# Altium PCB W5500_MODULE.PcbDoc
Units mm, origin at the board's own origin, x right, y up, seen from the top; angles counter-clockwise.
Board outline 30 x 34 mm, 2 copper layers (Top Layer, Bottom Layer); 44 components, 75 nets, 250 pads, 86 vias.
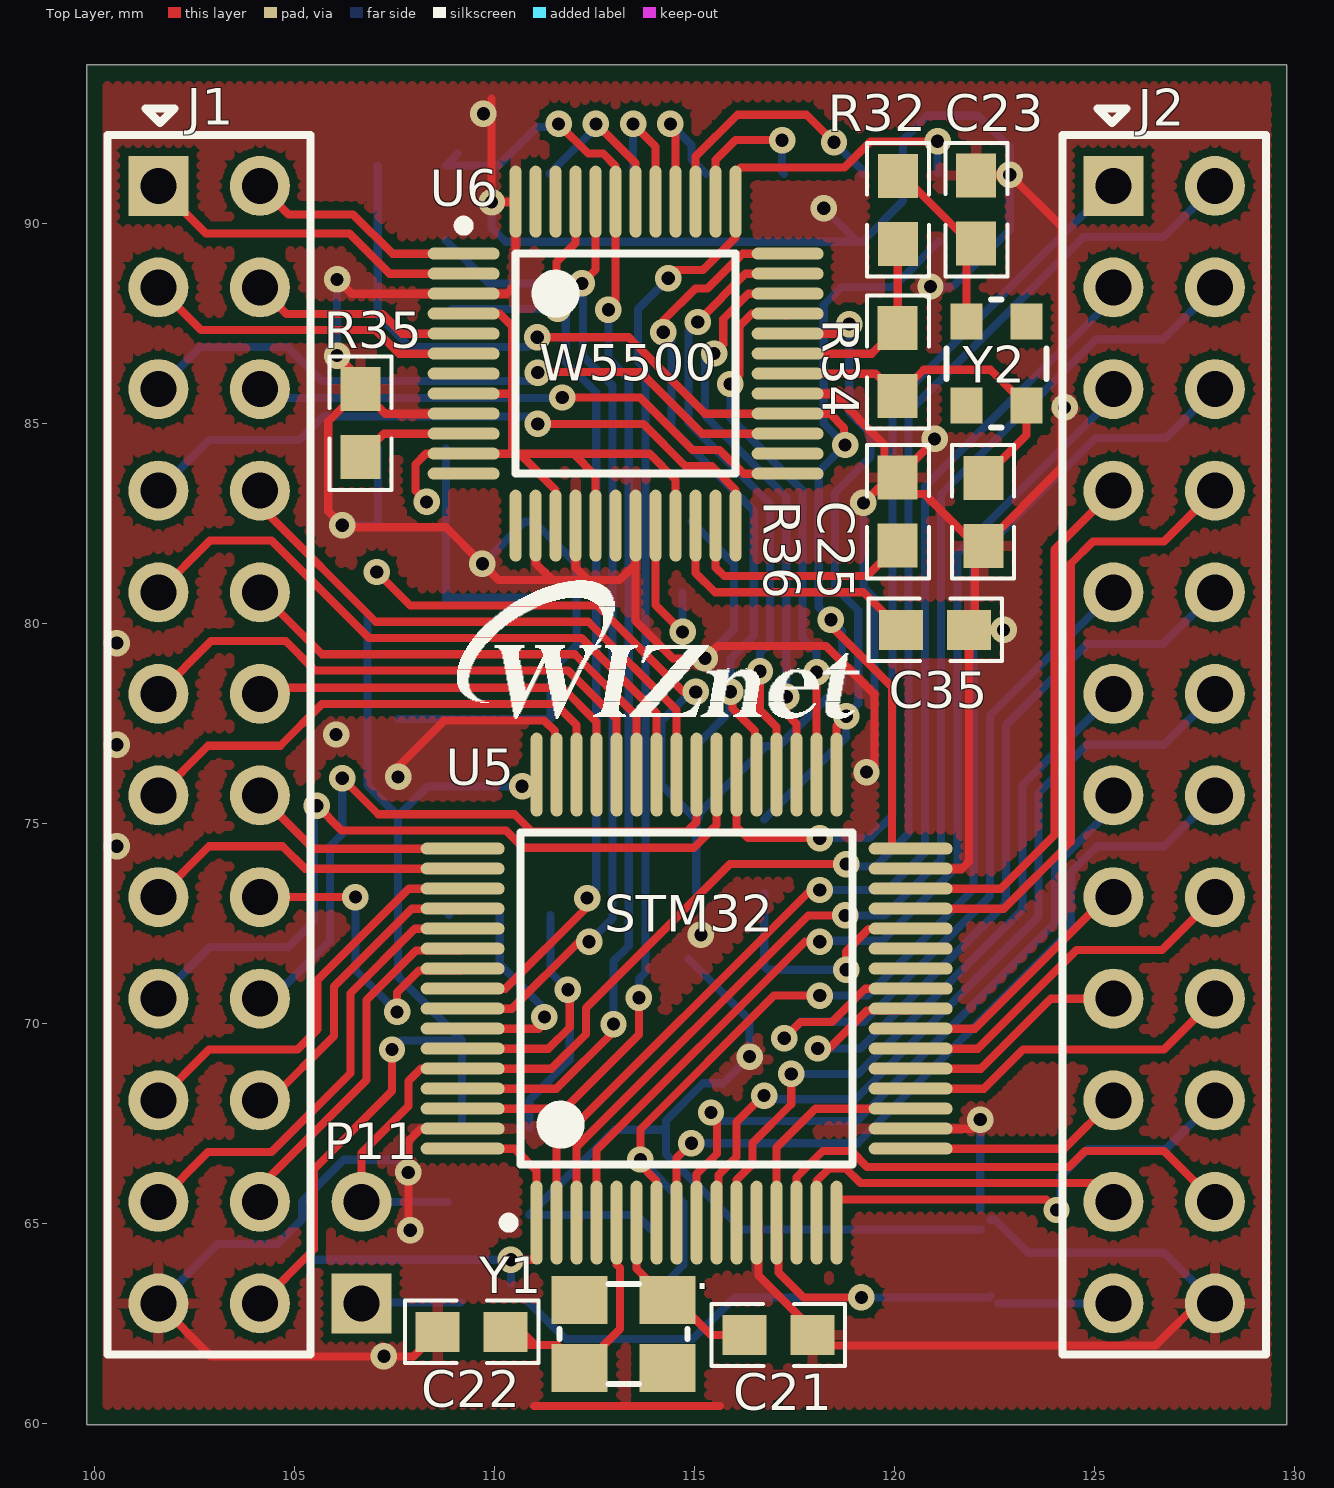
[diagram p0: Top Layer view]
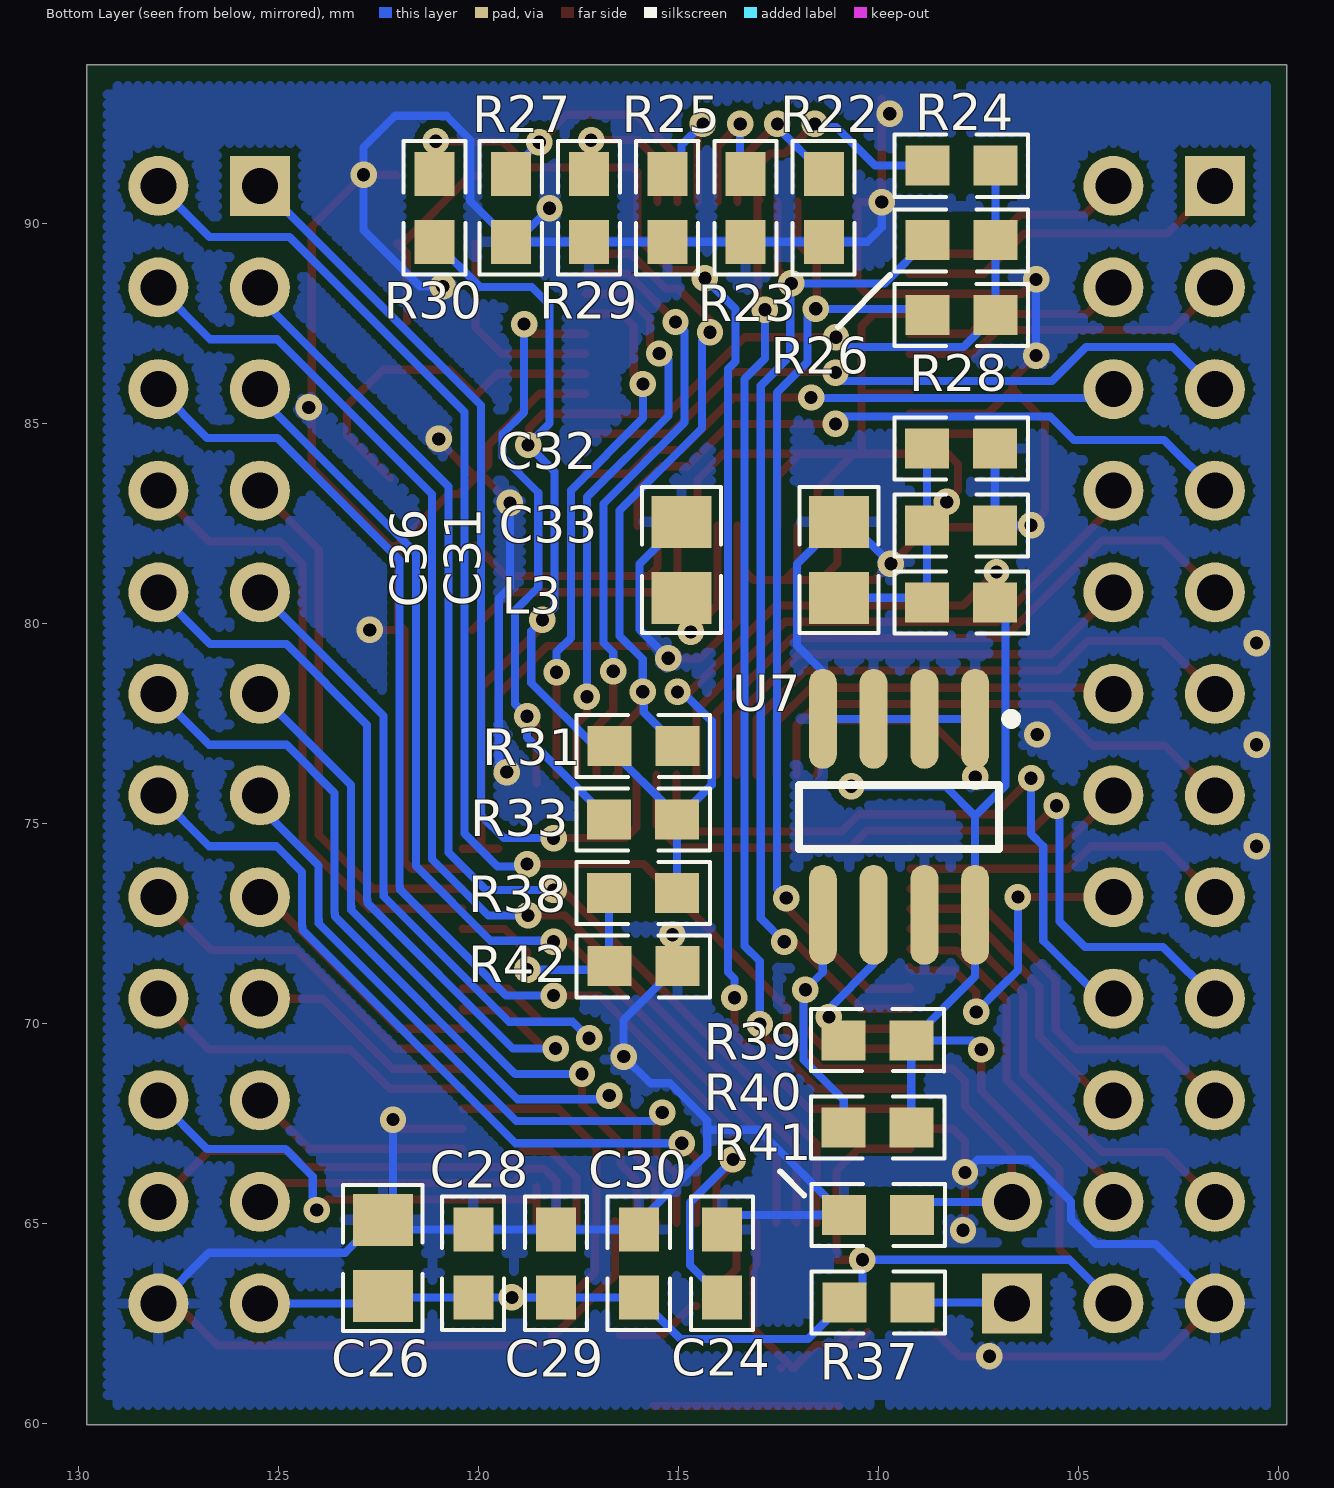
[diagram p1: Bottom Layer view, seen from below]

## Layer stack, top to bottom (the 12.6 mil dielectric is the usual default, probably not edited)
Top Layer: signal copper 0.0356
Dielectric: dielectric 0.32, FR-4, Dk 4.8
Bottom Layer: signal copper 0.0356

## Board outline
99.81,59.963 129.806,59.963 129.806,93.961 99.81,93.961

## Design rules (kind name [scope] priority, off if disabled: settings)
Clearance [All] p1: gap=0.203
PolygonConnect [IsVia] p1: connectstyle=Direct reliefconductorwidth=0.254 reliefentries=4 polygonreliefangle="90 Angle"
PolygonConnect PolygonConnect_1 [All] p2: connectstyle=Relief reliefconductorwidth=0.254 reliefentries=4 polygonreliefangle="90 Angle"
RoutingVias [All] p1: holewidth=0.33 width=0.66 viastyle="Through Hole" minholewidth=0.33 minwidth=0.66 maxholewidth=0.33 maxwidth=0.66
SilkscreenOverComponentPads [All] p1: minsilkscreentomaskgap=0.254
SolderMaskExpansion [All] p1: expansion=0.102
TestPointUsage [All] p1: valid=0 allowmultiple=FALSE
Testpoint [All] p1: side=15 testpointundercomponent=TRUE minsize=1.016 maxsize=2.54 preferedsize=1.524 minholesize=0 maxholesize=1.016 preferedholesize=0.813 testpointgrid=0.025 style=1023 order=0123456789
Width [All] p1: maxlimit=0.203 minlimit=0.203 preferedwidth=0.203
23 further rules are at their usual default settings.

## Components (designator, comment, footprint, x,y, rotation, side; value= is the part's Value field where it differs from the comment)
C21 "Cap" CR0603 117.069,62.332 r0 top
C22 "Cap" CR0603 109.474,62.154 r180 top
C23 "Cap" CR0603 121.92,90.305 r90 top
C24 "Cap" CR0603 113.792,64.033 r270 bottom
C25 "Cap" CR0603 122.352,82.821 r270 top
C26 "Cap2" CR0805 122.453,64.16 r90 bottom
C28 "Cap" CR0603 120.015,64.033 r270 bottom
C29 "Cap" CR0603 117.945,64.033 r270 bottom
C30 "Cap" CR0603 115.875,64.033 r270 bottom
C31 "Cap2" CR0805 111.049,81.61 r90 bottom
C32 "Cap" CR0603 107.908,84.237 r0 bottom
C33 "Cap" CR0603 107.908,82.314 r0 bottom
C35 "Cap" CR0603 121.056,79.705 r180 top
C36 "Cap2" CR0805 114.986,81.61 r90 bottom
J1 "Header 12X2" HDR2X12 101.6,90.932 r270 top locked
J2 "Header 12X2" HDR2X12 125.476,90.932 r270 top locked
L3 "Inductor" cr0603 107.908,80.391 r0 bottom
P11 "2.0间距焊盘" HDR1X2 106.68,62.992 r90 top locked
R22 "Res1" CR0603 111.252,90.424 r270 bottom
R23 "Res1" CR0603 113.208,90.424 r270 bottom
R24 "Res1" CR0603 107.975,91.567 r180 bottom
R25 "Res1" CR0603 115.164,90.424 r270 bottom
R26 "Res1" CR0603 107.975,89.7 r180 bottom
R27 "Res1" CR0603 119.075,90.424 r270 bottom
R28 "Res1" CR0603 107.975,87.833 r180 bottom
R29 "Res1" CR0603 117.119,90.424 r270 bottom
R30 "Res1" CR0603 120.98,90.424 r270 bottom
R31 "Res1" CR0603 115.926,77.058 r180 bottom
R32 "Res1" CR0603 120.218,90.373 r270 top
R33 "Res1" CR0603 115.858,74.962 r0 bottom
R34 "Res1" CR0603 119.957,86.495 r90 top
R35 "Res1" CR0603 106.528,84.963 r90 top
R36 "Res1" CR0603 119.957,82.753 r90 top
R37 "Res1" CR0603 110.05,63.144 r180 bottom
R38 "Res1" CR0603 115.858,73.126 r0 bottom
R39 "Res1" CR0603 110.002,69.444 r0 bottom
R40 "Res1" CR0603 109.992,67.259 r0 bottom
R41 "Res1" CR0603 109.982,65.075 r0 bottom
R42 "Res1" CR0603 115.926,71.552 r180 bottom
U5 "STM32F103RC" LQFP64_M 114.808,70.612 r90 top locked
U6 "W5500" TQFP48_N 113.284,86.487 r0 top locked
U7 "EEPROM" "8 pin SOIC_M" 109.499,75.159 r270 bottom locked
Y1 "XTAL 8.0MHz" 4pin晶振（FA238）#1 113.233,62.23 r180 top
Y2 "XTAL 25.0MHz" 4pin晶振（FA238）#2 122.55,86.488 r90 top

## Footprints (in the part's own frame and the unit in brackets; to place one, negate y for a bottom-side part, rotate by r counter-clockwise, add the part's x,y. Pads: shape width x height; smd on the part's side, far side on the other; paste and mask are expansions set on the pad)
4pin晶振（FA238）#1 [mm] "4pin晶振（FA238）"
  rect 1.4x1.2 smd: 1(-1.1,-0.85) 2(1.1,-0.85) 3(1.1,0.85) 4(-1.1,0.85)
  silkscreen extent -1.6,-1.25 1.6,1.25
4pin晶振（FA238）#2 [mm]
  rect 0.9x0.8 smd: 1(-1.05,-0.75) 2(1.05,-0.75) 3(1.05,0.75) 4(-1.05,0.75)
  silkscreen extent -1.6,-1.25 1.6,1.25
"8 pin SOIC_M" [mm] "8-Pin Small Outline Integrated Circuit 1.27 mm Pitch, IPC Low Density"
  oval 2.5x0.7 smd: 1(-2.45,1.905) 2(-2.45,0.635) 3(-2.45,-0.635) 4(-2.45,-1.905) 5(2.45,-1.905) 6(2.45,-0.635) 7(2.45,0.635) 8(2.45,1.905)
  silkscreen extent -2.57,-2.5 0.8,2.93, body extent -2,-2.5 2,2.5, height 1.91
CR0603 [mm]
  rect 1.1x1 smd: 1(-0.811,-0.127) 2(0.889,-0.127)
  silkscreen extent -1.63,-0.91 1.7,0.65
cr0603 [mm]
  rect 1.1x1 smd: 1(-0.811,-0.127) 2(0.889,-0.127)
  silkscreen extent -1.63,-0.91 1.7,0.65
CR0805 [mm]
  rect 1.3x1.5 smd: 1(-0.975,-0.051) 2(0.925,-0.051)
  silkscreen extent -1.85,-1.04 1.8,0.94
HDR1X2 [mm] "Connector; Header; 2 Position"
  rect 1.5x1.5 hole 0.9: 1(0,0)
  round 1.5 hole 0.9: 2(2.54,0)
HDR2X12 [mm] "Connector; Header; 12x2 Position"
  rect 1.5x1.5 hole 0.9: 1(0,0)
  round 1.5 hole 0.9: 2(0,2.54) 3(2.54,0) 4(2.54,2.54) 5(5.08,0) 6(5.08,2.54) 7(7.62,0) 8(7.62,2.54) 9(10.16,0) 10(10.16,2.54) 11(12.7,0) 12(12.7,2.54) 13(15.24,0) 14(15.24,2.54) 15(17.78,0) 16(17.78,2.54) 17(20.32,0) 18(20.32,2.54) 19(22.86,0) 20(22.86,2.54) 21(25.4,0) 22(25.4,2.54) 23(27.94,0) 24(27.94,2.54)
  silkscreen extent -1.27,-1.27 29.21,3.81
LQFP64_M [mm] "Thin QFP, 64-Leads, Body 10x10mm, Pitch 0.5mm, IPC Low Density"
  oval 2.1x0.3 smd: 1(-5.6,3.75) 2(-5.6,3.25) 3(-5.6,2.75) 4(-5.6,2.25) 5(-5.6,1.75) 6(-5.6,1.25) 7(-5.6,0.75) 8(-5.6,0.25) 9(-5.6,-0.25) 10(-5.6,-0.75) 11(-5.6,-1.25) 12(-5.6,-1.75) 13(-5.6,-2.25) 14(-5.6,-2.75) 15(-5.6,-3.25) 16(-5.6,-3.75) 33(5.6,-3.75) 34(5.6,-3.25) 35(5.6,-2.75) 36(5.6,-2.25) 37(5.6,-1.75) 38(5.6,-1.25) 39(5.6,-0.75) 40(5.6,-0.25) 41(5.6,0.25) 42(5.6,0.75) 43(5.6,1.25) 44(5.6,1.75) 45(5.6,2.25) 46(5.6,2.75) 47(5.6,3.25) 48(5.6,3.75)
  oval 0.3x2.1 smd: 17(-3.75,-5.6) 18(-3.25,-5.6) 19(-2.75,-5.6) 20(-2.25,-5.6) 21(-1.75,-5.6) 22(-1.25,-5.6) 23(-0.75,-5.6) 24(-0.25,-5.6) 25(0.25,-5.6) 26(0.75,-5.6) 27(1.25,-5.6) 28(1.75,-5.6) 29(2.25,-5.6) 30(2.75,-5.6) 31(3.25,-5.6) 32(3.75,-5.6) 49(3.75,5.6) 50(3.25,5.6) 51(2.75,5.6) 52(2.25,5.6) 53(1.75,5.6) 54(1.25,5.6) 55(0.75,5.6) 56(0.25,5.6) 57(-0.25,5.6) 58(-0.75,5.6) 59(-1.25,5.6) 60(-1.75,5.6) 61(-2.25,5.6) 62(-2.75,5.6) 63(-3.25,5.6) 64(-3.75,5.6)
  silkscreen extent -5.72,-4.15 4.15,4.57, body extent -5,-5 5,5, height 1.6
TQFP48_N [mm] "Thin QFP, 48-Leads, Body 7x7mm, Pitch 0.5mm, IPC Medium Density"
  oval 1.8x0.3 smd: 1(-4.05,2.75) 2(-4.05,2.25) 3(-4.05,1.75) 4(-4.05,1.25) 5(-4.05,0.75) 6(-4.05,0.25) 7(-4.05,-0.25) 8(-4.05,-0.75) 9(-4.05,-1.25) 10(-4.05,-1.75) 11(-4.05,-2.25) 12(-4.05,-2.75) 25(4.05,-2.75) 26(4.05,-2.25) 27(4.05,-1.75) 28(4.05,-1.25) 29(4.05,-0.75) 30(4.05,-0.25) 31(4.05,0.25) 32(4.05,0.75) 33(4.05,1.25) 34(4.05,1.75) 35(4.05,2.25) 36(4.05,2.75)
  oval 0.3x1.8 smd: 13(-2.75,-4.05) 14(-2.25,-4.05) 15(-1.75,-4.05) 16(-1.25,-4.05) 17(-0.75,-4.05) 18(-0.25,-4.05) 19(0.25,-4.05) 20(0.75,-4.05) 21(1.25,-4.05) 22(1.75,-4.05) 23(2.25,-4.05) 24(2.75,-4.05) 37(2.75,4.05) 38(2.25,4.05) 39(1.75,4.05) 40(1.25,4.05) 41(0.75,4.05) 42(0.25,4.05) 43(-0.25,4.05) 44(-0.75,4.05) 45(-1.25,4.05) 46(-1.75,4.05) 47(-2.25,4.05) 48(-2.75,4.05)
  silkscreen extent -4.17,-2.75 2.75,3.57, body extent -3.5,-3.5 3.5,3.5, height 1.6

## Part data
C21 C22 C23 C24 C25 C26 C28 C29 C30 C31 C32 C33 C35 C36: "Capacitor"
J1 J2: "Header, 12-Pin, Dual row"
P11: library part "Header 2", "Header, 2-Pin"
R22 R23 R24 R25 R26 R27 R28 R29 R30 R31 R32 R33 R34 R35 R36 R37 R38 R39 R40 R41 R42: "Resistor"
U7: library part 24XX01, "24XX01"
Y1 Y2: library part XTAL, "Crystal Oscillator"

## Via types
v1: diameter 0.66, hole 0.33, Top Layer to Bottom Layer, tented both sides, 81 vias
v2: diameter 0.66, hole 0.33, Top Layer to Bottom Layer, 5 vias

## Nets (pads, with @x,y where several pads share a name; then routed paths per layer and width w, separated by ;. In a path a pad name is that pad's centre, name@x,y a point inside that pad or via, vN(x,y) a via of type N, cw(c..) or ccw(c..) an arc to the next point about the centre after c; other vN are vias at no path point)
ACTLED: J1.5 U6.27 | length 16.9
  Top Layer w0.203: v1@111.346,86.276 113.657,86.276 115.196,84.737 U6.27
  Bottom Layer w0.203: J1.5 102.655,86.907 104.826,86.907 105.677,86.055 v1@111.125,86.055
  other v1: 111.086,86.264
BOOT0: J2.2 P11.2 R41.1 U5.60 | length 42.2
  Top Layer w0.203: P11.2@106.74,65.532 P11.2 106.68,66.751 107.853,67.924 107.853,68.55 108.165,68.862 U5.60 ; U5.60@109.163,68.817 U5.60 ; v1(118.796,73.977) 115.887,73.977 112.293,70.383 112.293,69.723 111.432,68.862 U5.60
  Bottom Layer w0.203: P11.2@107.01,65.202 P11.2 R41.1@108.841,65.532 ; v1@118.859,73.914 119.532,73.914 120.357,74.739 120.357,85.28 124.732,89.654 126.374,89.654 ; 126.374,89.651 126.735,89.651 J2.2
DUPLED: U6.26
GND: C21.2 C22.2 C23.2 C24.1 C25.2 C26.2 C28.1 C29.1 C30.1 C31.2 C32.1 C33.1 C35.1 C36.2 J1.23 J2.24 R22.2 R23.2 R25.2 R27.2 R29.2 R35.2 R36.2 R41.2 R42.2 U5.12 U5.18 U5.31 U5.47 U5.63 U6.3 U6.9 U6.14 U6.16 U6.19 U6.29 U6.48 U7.1 U7.2 U7.3 U7.4 U7.7 | length 199.6
  Top Layer w0.203: J1.23 102.921,61.671 v1(107.239,61.671) 107.975,61.671 C22.2 ; v1(106.07,86.69) 106.655,86.106 R35.2 ; v1(106.07,88.595) 106.429,88.237 U6.3 110.31,88.237 110.534,88.461 U6.48 ; v1@107.606,76.417 108.755,77.567 111.246,77.567 111.513,77.3 111.513,76.257 U5.47 ; v1(107.899,64.821) 107.853,64.867 107.853,67.05 108.165,67.362 U5.63 ; U6.9 107.27,85.237 R35.2 ; 109.931,93.116 v1(109.931,90.526) U6.48@110.523,90.526 ; 110.998,60.427 115.646,60.427 ; U6.14 111.034,81.498 111.455,81.077 ; U6.16 112.034,81.387 112.344,81.077 ; U6.19 113.534,81.479 ; U5.12@116.603,65.057 U5.12 116.603,64.967 116.603,63.695 116.883,63.416 118.094,62.205 C21.2@118.186,62.205 ; U6.29 118.479,85.737 119.758,84.458 119.758,83.968 R36.2 ; C21.2@118.454,61.937 126.531,61.937 127.586,62.992 J2.24 ; v1(119.228,83.007) 119.863,83.642 R36.2 ; v1(119.304,76.276) 119.507,76.479 119.507,78.22 118.296,79.431 115.575,79.431 v1(115.265,79.121) 114.469,79.121 113.534,80.056 113.534,81.479 ; U5.31 121.69,73.862 121.867,74.039 C35.1 ; v1(121.006,84.607) 121.006,84.563 R36.2 ; 121.845,67.362 U5.18 121.921,67.362 v1(122.149,67.589) ; C25.2@121.979,81.932 C25.2 ; C23.2 122.064,91.211 v1(122.885,91.211) 124.181,89.916 124.181,83.888 C25.2 ; v1(122.733,79.832) C35.1 ; R35.2 105.85,85.047 105.85,82.796 v1(106.197,82.448) 106.248,82.398 108.788,82.398 v1(109.703,81.483) 110.109,81.077 111.455,81.077 ; 111.455,81.077 112.344,81.077 ; 112.344,81.077 113.132,81.077 113.534,81.479 ; R36.2 120.494,83.233 120.754,83.233 122.055,81.932 C25.2 ; C35.1 122.022,79.986 122.022,81.729 C25.2
  Bottom Layer w0.203: J1.23 103.085,64.477 104.577,64.477 105.195,65.095 105.195,65.539 106.243,66.587 107.53,66.587 v1(107.848,66.269) ; v1(106.07,86.69) v1(106.07,88.595) ; v1@106.205,82.441 C33.1 C32.1 ; U7.1 U7.2 U7.3 U7.4 111.404,78.791 112.053,79.439 112.053,81.48 C31.2 110.754,82.535 v1(109.703,81.483) ; U7.7@108.839,72.734 U7.7 ; v1(109.931,90.526) 109.931,89.891 110.287,89.535 R22.2 R23.2 R25.2 R29.2 R27.2@119.075,89.535 ; C24.1 113.562,65.202 R41.2 113.005,67.335 114.293,67.335 ; R42.2@114.859,71.603 R42.2 116.383,70.079 v1(116.383,69.164) 115.716,68.497 115.22,68.497 114.293,67.571 114.293,67.335 ; C36.2 115.99,81.48 115.99,79.846 v1(115.265,79.121) ; v1(118.237,90.373) R27.2@119.075,89.535 ; v1@119.202,76.225 119.506,76.529 119.506,80.621 119.228,80.899 v1(119.228,83.007) ; v1(120.904,88.417) 121.471,88.417 122.885,89.832 v1(122.885,91.211) 122.885,91.897 122.098,92.684 120.819,92.684 120.218,92.084 120.218,90.551 R27.2 R27.2@119.075,89.535 ; C26.2@122.149,65.339 v1(122.149,67.589) ; C26.2@122.162,64.844 C28.1 C29.1 C30.1 116.002,65.024 114.293,66.733 114.293,67.335 ; C26.2 122.519,65.085 123.342,64.262 124.866,64.262 ; 124.485,64.262 124.866,64.262 ; J2.24 126.746,64.262 124.866,64.262
  other v1: 115.164,72.212 100.559,74.422 107.594,76.155 100.559,76.962 106.045,77.216 100.559,79.502 124.257,85.395 109.728,92.735
I2C_SCL: R39.2 U5.58 U7.6 | length 8.7
  Top Layer w0.203: U5.58@109.253,69.907 U5.58 ; U5.58@110.251,69.862 U5.58 ; 110.756,69.862 U5.58 ; v1@111.112,69.862 U5.58
  Bottom Layer w0.203: U7.6@110.134,71.78 U7.6 110.134,71.476 111.252,70.358 R39.2@111.252,69.931
  other v1: 111.252,70.155
I2C_SDA: R40.2 U5.59 U7.5 | length 10.6
  Top Layer w0.203: U5.59 111.357,69.362 111.887,69.892 v1@111.887,70.79
  Bottom Layer w0.203: R40.2 110.881,68.079 111.887,69.085 111.887,70.79 v1(111.839,70.838) 111.404,71.272 U7.5 U7.5@111.404,71.806
JTDI: J1.15 U5.50 | length 8.4
  Top Layer w0.203: J1.15 102.87,74.422 104.707,74.422 105.267,73.862 U5.50
LINKLED: J1.6 U6.25 | length 14.4
  Top Layer w0.203: v1@111.943,85.641 113.64,85.641 114.95,84.331 115.634,84.331 116.228,83.737 U6.25
  Bottom Layer w0.203: J1.6@104.546,86.258 J1.6 104.363,85.629 v1@111.696,85.629
  other v1: 111.696,85.641
NetC23_1: C23.1 R32.1 Y2.3 | length 4.8
  Top Layer w0.203: R32.1 120.22,91.184 121.91,89.494 C23.1 ; Y2.3 121.8,89.248 C23.1 ; C23.1@121.986,89.494 C23.1
NetC25_1: C25.1 R34.1 U6.30 Y2.1 | length 9.4
  Top Layer w0.203: U6.30 119.532,86.237 R34.1 ; R34.1@120.155,85.684 R34.1 ; C25.1 123.3,84.707 Y2.1 ; Y2.1@123.3,85.2 Y2.1 ; R34.1 120.735,86.335 122.403,86.335 Y2.1
NetC35_2: C35.2 U6.22 | length 6.9
  Top Layer w0.203: U6.22 115.034,81.257 115.519,80.772 119.228,80.772 C35.2
NetC36_1: C36.1 U6.20 | length 3.9
  Top Layer w0.203: U6.20 114.034,80.454 v1(114.706,79.781)
  Bottom Layer w0.203: v1(114.706,79.781) C36.1@114.706,80.768
NetP11_1: P11.1 R37.2 | length 2.5
  Bottom Layer w0.203: P11.1 106.705,63.017 R37.2
NetR22_1: R22.1 U6.42 | length 4
  Top Layer w0.203: v1@112.558,92.481 113.534,91.505 U6.42
  Bottom Layer w0.203: R22.1@111.404,91.26 R22.1 v1@112.549,92.405
  other v1: 112.539,92.481
NetR23_1: R23.1 U6.41 | length 3.3
  Top Layer w0.203: v1(113.47,92.481) 114.034,91.918 U6.41
  Bottom Layer w0.203: R23.1@113.47,91.37 v1(113.47,92.481)
NetR25_1: R25.1 U6.40 | length 3.6
  Top Layer w0.203: v1(114.402,92.481) 114.534,92.349 U6.40
  Bottom Layer w0.203: v1(114.402,92.481) 114.933,91.95 114.933,91.592 R25.1
NetR27_1: R27.1 U6.39 | length 6.3
  Top Layer w0.203: U6.39 115.034,91.669 116.075,92.71 117.805,92.71 v1(118.491,92.024)
  Bottom Layer w0.203: v1@118.542,91.973 119.202,91.313 R27.1
NetR29_1: R29.1 U6.38 | length 3.9
  Top Layer w0.203: U6.38 115.534,91.582 116.027,92.075 v1(117.196,92.075) v1@117.348,92.075
  Bottom Layer w0.203: v1(117.196,92.075) 117.196,91.286 R29.1
NetR32_2: R32.2 R34.2 U6.31 | length 5.1
  Top Layer w0.203: U6.31 119.437,86.737 R34.2 120.084,89.477 R32.2
NetR35_1: R35.1 U6.10 | length 2.8
  Top Layer w0.203: R35.1 107.24,84.737 U6.10
NetR36_1: R36.1 U6.23 | length 6
  Top Layer w0.203: U6.23 115.534,81.392 115.748,81.178 119.321,81.178 R36.1
NRESET: C24.2 J2.6 U5.7 | length 33.6
  Top Layer w0.203: v1@113.587,66.592 113.587,66.527 114.058,66.055 U5.7 ; v1(113.652,66.592) 113.652,67.348 116.992,70.688 v1(118.135,70.688) ; v1@118.118,70.671 v1(118.135,70.688) ; v1@118.161,70.688 v1(118.135,70.688)
  Bottom Layer w0.203: v1(113.652,66.592) 114.724,65.521 114.724,63.949 C24.2 ; v1@118.161,70.688 119.326,70.688 121.974,73.337 121.974,73.423 121.983,73.431 121.983,81.581 125.035,84.633 126.797,84.633 J2.6
PA0: J2.22 U5.14 | length 12.7
  Top Layer w0.203: U5.14 117.558,66.148 118.212,66.802 118.925,66.802 119.32,66.407 124.37,66.407 124.765,66.802 126.746,66.802 J2.22
PA1: J2.21 U5.15 | length 8.9
  Top Layer w0.203: U5.15 118.058,66.055 118.373,66.37 118.376,66.367 118.785,66.367 119.151,66.001 125.007,66.001 J2.21
PA2: J2.20 U5.16 | length 12
  Top Layer w0.203: U5.16 U5.16@118.558,65.904 ; U5.16@118.593,65.594 123.788,65.594 v1(124.054,65.329)
  Bottom Layer w0.203: v1(124.054,65.329) 124.155,65.43 124.155,66.167 124.841,66.853 126.797,66.853 J2.20
PA3: J2.19 U5.17 | length 5.6
  Top Layer w0.203: U5.17 124.25,66.862 125.46,68.072 J2.19
PA4: J2.18 U5.20 | length 8.5
  Top Layer w0.203: U5.20 122.239,68.362 123.219,69.342 126.746,69.342 J2.18
PA5: J2.17 U5.21 | length 5.8
  Top Layer w0.203: U5.21 122.164,68.862 123.914,70.612 J2.17
PA6: J2.16 U5.22 | length 9.2
  Top Layer w0.203: U5.22 122.089,69.362 124.559,71.831 126.695,71.831 J2.16
PA7: J2.15 U5.23 | length 6.4
  Top Layer w0.203: U5.23 122.015,69.862 125.305,73.152 J2.15
PA8: J1.8 U5.41 | length 14.5
  Top Layer w0.203: J1.8 104.35,83.102 104.35,82.721 107.036,80.035 112.348,80.035 114.558,77.825 U5.41
PA9: J1.9 U5.42 | length 16.3
  Top Layer w0.203: J1.9 102.895,82.067 104.429,82.067 106.867,79.629 112.179,79.629 114.058,77.75 U5.42
PA10: J1.10 U5.43 | length 12.2
  Top Layer w0.203: J1.10 105.689,79.223 108.509,79.223 112.011,79.223 113.558,77.676 U5.43
PA11: J1.11 U5.44 | length 14.2
  Top Layer w0.203: J1.11 102.921,79.553 104.784,79.553 105.521,78.816 111.843,78.816 113.058,77.601 U5.44
PA12: J1.12 U5.45 | length 10.2
  Top Layer w0.203: J1.12 104.292,78.384 111.7,78.384 112.558,77.526 U5.45
PA13: J1.13 U5.46 | length 12.9
  Top Layer w0.203: J1.13 102.845,76.937 104.648,76.937 105.689,77.978 111.531,77.978 112.058,77.451 U5.46
PA14: J1.14 U5.49 | length 5.6
  Top Layer w0.203: J1.14 105.47,74.362 U5.49
PB2/BOOT1: R38.2 R42.1 U5.28 | length 6.2
  Top Layer w0.203: v1(118.796,71.336) 118.796,71.793 119.356,72.353 120.399,72.353 U5.28
  Bottom Layer w0.203: R42.1 116.826,71.336 v1(118.796,71.336) ; R42.1@116.747,71.435 R38.2
PB3: J1.16 U5.55 | length 8.2
  Top Layer w0.203: J1.16@104.191,73.203 J1.16 v1(106.528,73.152) ; v1(107.569,70.282) 107.569,70.766 108.12,71.317 109.163,71.317 U5.55 U5.55@109.253,71.407
  Bottom Layer w0.203: v1(106.528,73.152) 106.528,71.323 106.948,70.903 v1(107.569,70.282) ; v1@106.578,73.152 v1@106.578,73.203
PB10: J2.8 U5.29 | length 16
  Top Layer w0.203: U5.29 122.738,72.862 124.411,74.535 124.411,81.485 124.968,82.042 126.746,82.042 J2.8
PB11: J2.7 U5.30 | length 13.4
  Top Layer w0.203: U5.30 122.663,73.362 124.005,74.704 124.005,81.841 J2.7
PC0: J2.14 U5.8 | length 19.7
  Top Layer w0.203: U5.8 114.558,66.628 v1(114.928,66.998)
  Bottom Layer w0.203: v1@114.935,67.005 v1(114.928,66.998) 119.084,66.998 124.413,72.327 124.413,72.413 124.421,72.421 124.421,73.777 125.066,74.422 126.746,74.422 J2.14
PC1: J2.13 U5.9 | length 17.6
  Top Layer w0.203: U5.9 115.058,66.23 115.563,66.735 115.563,67.622 v1(115.418,67.767)
  Bottom Layer w0.203: v1(115.418,67.767) 115.629,67.556 119.067,67.556 124.006,72.495 124.006,72.581 124.015,72.59 124.015,73.945 125.476,75.407 J2.13
PC2: J2.12 U5.10 | length 21
  Top Layer w0.203: U5.10 115.603,65.057 115.603,66.201 116.053,66.65 116.053,67.529 116.714,68.191 v1(116.745,68.191)
  Bottom Layer w0.203: v1@116.744,68.191 116.837,68.097 119.034,68.097 123.6,72.663 123.6,72.75 123.608,72.758 123.608,75.755 124.816,76.962 126.746,76.962 J2.12
PC3: J2.11 U5.11 | length 18.1
  Top Layer w0.203: U5.11 116.058,66.081 116.459,66.482 116.459,67.006 117.424,67.972 v1(117.424,68.732)
  Bottom Layer w0.203: v1(117.424,68.732) 119.094,68.732 123.194,72.832 123.194,72.918 123.202,72.926 123.202,75.958 J2.11
PC4: J2.10 U5.24 | length 20
  Top Layer w0.203: v1(118.085,69.367) 118.37,69.367 119.32,70.317 120.363,70.317 U5.24
  Bottom Layer w0.203: v1(118.085,69.367) 119.154,69.367 122.787,73 122.787,73.086 122.796,73.095 122.796,77.457 124.816,79.477 126.721,79.477 J2.10
PC5: J2.9 U5.25 | length 19.2
  Top Layer w0.203: v1(117.246,69.621) 117.653,70.028 118.44,70.028 119.274,70.862 U5.25
  Bottom Layer w0.203: v1(117.246,69.621) 117.661,70.036 119.249,70.036 122.381,73.168 122.381,73.255 122.389,73.263 122.389,77.685 J2.9
PC7: J2.1 U5.38 | length 24.3
  Top Layer w0.203: U5.38 116.058,74.905 116.337,74.625 v1(118.135,74.625)
  Bottom Layer w0.203: v1(118.135,74.625) 119.38,74.625 119.951,75.196 119.951,75.628 119.951,85.448 122.369,87.867 ; 122.53,88.027 122.369,87.867 ; J2.1@125.173,91.235 J2.1 125.435,90.932 122.369,87.867
PC8: J1.17 U5.39 | length 20.4
  Top Layer w0.203: v1(105.562,75.438) 106.184,74.817 110.296,74.817 110.729,74.384 114.985,74.384 115.558,74.957 U5.39
  Bottom Layer w0.203: J1.17 102.895,71.907 104.851,71.907 ; 105.435,72.492 104.851,71.907 ; v1(105.562,75.438) 105.486,75.362 105.486,72.542 104.851,71.907
PC9: J1.18 U5.40 | length 17.9
  Top Layer w0.203: v1(106.197,76.124) 107.098,75.223 110.504,75.223 110.937,74.79 114.817,74.79 115.058,75.032 U5.40
  Bottom Layer w0.203: J1.18@104.14,71.196 J1.18 ; J1.18@104.267,70.612 J1.18 ; v1(106.197,76.124) 106.197,74.727 105.893,74.422 105.893,72.06 104.445,70.612 J1.18
PC10: J1.19 U5.51 | length 10.5
  Top Layer w0.203: J1.19 102.87,69.342 105.08,69.342 105.579,69.842 105.579,71.076 107.866,73.362 U5.51
PC11: J1.20 U5.52 | length 7.8
  Top Layer w0.203: J1.20 104.385,68.072 105.994,69.682 105.994,70.916 107.941,72.862 U5.52 U5.52@109.163,72.817
PC12: J1.21 U5.53 | length 11.6
  Top Layer w0.203: J1.21 102.845,66.777 104.429,66.777 106.401,68.748 106.401,70.747 108.015,72.362 U5.53
PC13: J2.3 U5.2 | length 30
  Top Layer w0.203: U5.2 111.558,66.978 117.91,73.33 v1(118.135,73.33)
  Bottom Layer w0.203: v1(118.135,73.33) 119.828,73.33 120.764,74.266 120.764,83.414 J2.3@125.46,88.11 ; J2.3@125.46,88.392 J2.3
PC14: J2.4 U5.3 | length 32.2
  Top Layer w0.203: U5.3@112.103,65.057 U5.3 112.058,66.903 117.85,72.695 v1(118.77,72.695)
  Bottom Layer w0.203: v1(118.77,72.695) 119.767,72.695 121.17,74.097 121.17,83.222 125.044,87.097 126.721,87.097 J2.4
PC15: J2.5 U5.4 | length 27.3
  Top Layer w0.203: U5.4 112.558,66.829 117.764,72.034 v1(118.135,72.034)
  Bottom Layer w0.203: v1(118.135,72.034) 118.161,72.06 119.707,72.06 121.576,73.929 121.576,81.749 125.476,85.649 J2.5
PD2: J1.22 U5.54 | length 9.1
  Top Layer w0.203: J1.22@104.156,65.532 J1.22 104.14,65.913 106.807,68.58 106.807,70.579 108.045,71.817 109.163,71.817 U5.54
RXN: J1.4 U6.5 | length 5.6
  Top Layer w0.203: J1.4 104.8,87.732 107.2,87.732 107.695,87.237 U6.5
RXP: J1.3 U6.6 | length 8.3
  Top Layer w0.203: J1.3 102.667,87.325 107.032,87.325 107.62,86.737 U6.6
SPDLED: J1.7 U6.24 | length 16.6
  Top Layer w0.203: v1@111.334,84.98 113.725,84.98 114.781,83.924 115.44,83.924 116.034,83.331 U6.24
  Bottom Layer w0.203: J1.7 102.87,84.582 105.131,84.582 105.717,85.169 110.898,85.169 v1(111.086,84.98)
TXN: J1.2 U6.1 | length 5.8
  Top Layer w0.203: J1.2 104.851,90.221 106.467,90.221 107.451,89.237 U6.1
TXP: J1.1 U6.2 | length 8.5
  Top Layer w0.203: J1.1 102.794,89.738 106.375,89.738 107.376,88.737 U6.2
VCC: C26.1 C28.2 C29.2 C30.2 J1.24 J2.23 L3.1 R24.2 R26.2 R28.2 R30.2 R31.1 R33.1 R37.1 R38.1 R39.1 R40.1 U5.1 U5.13 U5.19 U5.32 U5.48 U5.64 U6.28 U7.8 | length 124.7
  Top Layer w0.203: J1.24 105.486,64.338 105.486,66.345 107.442,68.301 v1(107.442,69.342) v1@107.442,69.367 ; v1(107.061,81.28) 107.899,80.442 108.026,80.442 112.573,80.442 114.732,78.283 v1(115.037,78.283) ; U5.64 110.506,66.862 111.058,66.31 U5.1 U5.1@111.058,64.297 ; v1(110.414,64.084) U5.1@111.049,64.084 ; v1(111.074,87.147) 113.36,87.147 113.908,86.599 ; 113.411,87.097 113.908,86.599 ; v1(118.415,80.086) 118.415,79.925 119.939,78.401 119.939,77.648 ; v1@118.745,84.48 118.745,84.881 118.389,85.237 U6.28 115.271,85.237 113.908,86.599 ; v1(119.177,63.144) 117.729,63.144 117.103,63.77 117.103,64.967 U5.13 117.058,66.893 118.027,67.862 U5.19 ; U5.32@119.516,74.362 120.126,74.362 U5.32 ; U5.32@119.939,74.362 119.939,77.648 ; 119.939,78.334 119.939,77.648
  Bottom Layer w0.203: J1.24@104.064,62.763 J1.24@104.064,62.916 ; J1.24 105.232,64.084 v1(110.414,64.084) R37.1@110.414,63.49 ; L3.1@106.832,80.2 106.832,75.946 107.594,75.184 ; R24.2 R26.2 R28.2 107.891,86.901 109.144,86.901 ; v1(107.442,69.342) 107.671,69.571 R39.1 ; U7.8@107.645,72.658 U7.8 ; R40.1@109.191,67.396 R39.1 ; 110.388,86.901 109.144,86.901 ; v1(110.693,75.921) 108.331,75.921 107.594,75.184 ; R37.1 111.775,62.103 114.96,62.103 C30.2 C29.2 C28.2 122.362,63.144 C26.1 ; v1(111.074,87.147) 110.828,86.901 109.144,86.901 ; v1(115.037,78.283) 114.908,78.283 114.182,77.557 114.182,75.954 R33.1 R38.1 ; R33.1@115.115,75.142 115.115,75.241 R31.1@116.77,76.897 ; R30.2 119.977,88.405 118.681,88.405 118.237,87.96 118.237,87.741 118.237,84.988 v1(118.77,84.455) 118.11,83.795 118.11,80.391 v1(118.415,80.086) 118.693,79.808 118.693,78.508 117.116,76.931 R31.1@116.804,76.931 ; C26.1@122.596,62.992 J2.23 J2.23@125.283,63.185 ; U7.8 107.594,71.168 R39.1 ; U7.8 107.594,75.184 ; R31.1@116.77,76.897 R31.1 R31.1@116.804,76.931 ; R31.1@116.77,76.897 R31.1@116.804,76.931
VCCA: C31.1 C32.2 C33.2 L3.2 U6.4 U6.8 U6.11 U6.15 U6.17 U6.21 | length 24.9
  Top Layer w0.203: v1(108.306,83.033) 108.026,83.312 108.026,83.972 108.291,84.237 U6.11 110.617,84.237 ; U6.8 110.349,85.737 ; U6.4 110.127,87.737 110.439,87.425 110.439,85.827 110.439,84.262 ; U6.15@111.489,82.482 U6.15 111.534,83.33 110.627,84.237 111.978,84.237 ; U6.17 112.534,83.681 111.978,84.237 ; U6.21 114.534,83.586 113.883,84.237 111.978,84.237
  Bottom Layer w0.203: L3.2 C33.2 C32.2 ; L3.2@108.913,80.635 C31.1
W5500_INTN: R31.2 U5.37 U6.36 | length 18.3
  Top Layer w0.203: v1(114.224,87.274) 114.224,87.563 115.028,88.367 115.332,88.367 116.071,89.106 116.075,89.106 116.205,89.237 U6.36 ; v2@115.951,78.288 115.951,77.862 116.513,77.3 116.513,76.257 U5.37
  Bottom Layer w0.203: v1(114.224,87.274) 114.427,87.071 114.427,84.874 116.484,82.816 116.484,79.68 115.905,79.101 v2(115.905,78.288) ; R31.2 115.882,77.776 v2@115.882,78.264
W5500_MISO: U5.35 U6.34 | length 14.2
  Top Layer w0.203: v1(115.494,86.741) 115.722,86.97 115.722,87.605 116.355,88.237 U6.34 ; v2(117.302,78.161) 117.302,77.735 117.558,77.479 U5.35
  Bottom Layer w0.203: v1@115.265,86.589 115.265,85.185 117.297,83.153 v2@117.297,78.166
W5500_MOSI: U5.36 U6.35 | length 15.8
  Top Layer w0.203: v1(115.087,87.528) 115.087,87.544 116.28,88.737 U6.35 ; v2(116.642,78.796) 116.642,77.82 117.058,77.404 ; 116.688,77.775 117.058,77.404 ; U5.36 117.058,77.404
  Bottom Layer w0.203: v1(115.087,87.528) 114.859,87.3 114.859,85.017 116.891,82.985 116.891,79.511 116.642,79.263 v2(116.642,78.796)
W5500_PMODE0: R28.1 U5.56 U6.45 | length 24.7
  Top Layer w0.203: U5.56@109.253,70.907 U5.56 110.283,70.862 v1@112.319,72.898 ; v1(111.582,87.859) 111.557,87.884 111.557,89.027 112.034,89.504 U6.45
  Bottom Layer w0.203: R28.1 108.939,87.859 v1(111.582,87.859) ; v1@111.785,87.655 111.785,86.531 112.547,85.769 112.547,73.355 v1(112.319,73.127)
W5500_PMODE1: R26.1 U5.57 U6.44 | length 27.6
  Top Layer w0.203: U5.57 110.443,70.362 112.116,72.034 v1(112.37,72.034) ; v1(112.192,88.494) 112.534,88.836 U6.44
  Bottom Layer w0.203: R26.1 109.866,88.494 111.252,88.494 ; v1@111.924,88.494 111.252,88.494 ; v1(112.37,72.034) 112.954,72.619 112.954,85.938 112.217,86.674 112.217,88.468 v1(112.192,88.494) 111.252,88.494
W5500_PMODE2: R24.1 U5.61 U6.43 | length 32
  Top Layer w0.203: U5.61 111.557,68.362 112.979,69.784 v1(112.979,69.977) ; v1(111.608,92.481) 112.347,91.742 112.722,91.742 113.034,91.43 U6.43 ; v1(112.852,87.833) 113.034,88.015 U6.43 ; U6.43@112.989,90.582 U6.43 ; U6.43@113.034,90.516 U6.43
  Bottom Layer w0.203: R24.1@109.088,91.742 R24.1 110.103,91.44 111.068,92.405 v1@111.608,92.405 ; v1(112.852,87.833) 112.852,86.614 113.36,86.106 113.36,71.933 112.979,71.552 112.979,70.841 v1(112.979,69.977)
W5500_RST: R30.1 U5.62 U6.37 | length 34.4
  Top Layer w0.203: U5.62 111.762,67.862 113.614,69.714 v1(113.614,70.637) ; v1(114.351,88.621) 114.559,88.829 115.219,88.829 116.034,89.644 U6.37 116.034,91.269 116.154,91.389 118.754,91.389 119.404,92.039 121.072,92.039 v1(121.082,92.049)
  Bottom Layer w0.203: v1(113.614,70.637) 113.614,71.111 113.775,71.272 113.775,86.351 113.589,86.538 113.589,87.859 v1(114.351,88.621) ; R30.1@121.082,91.26 v1(121.082,92.049)
W5500_SCLK: U5.34 U6.33 | length 13.6
  Top Layer w0.203: v1(115.9,85.979) 116.129,86.208 116.129,87.425 116.441,87.737 U6.33 U6.33@117.289,87.692 ; U5.34 v2(118.058,78.771)
  Bottom Layer w0.203: v1(115.9,85.979) 115.9,85.125 117.704,83.321 117.704,79.629 118.058,79.275 v2(118.058,78.771)
W5500_SCSN: R33.2 U5.33 U6.32 | length 17.6
  Top Layer w0.203: U6.32 118.631,87.237 v1(118.872,87.478) ; U5.33@118.558,75.993 U5.33 118.558,77.435 v2(118.796,77.673)
  Bottom Layer w0.203: R33.2 118.796,77.137 v2(118.796,77.673) 119.099,77.977 119.099,80.316 118.516,80.899 118.516,83.261 119.405,84.15 119.405,84.734 118.872,85.268 v1(118.872,87.478)
XTAL_N: C21.1 U5.6 Y1.1 | length 4.5
  Top Layer w0.203: U5.6@113.603,64.967 U5.6 113.558,63.861 114.333,63.086 Y1.1 ; Y1.1@114.566,62.929 114.69,62.929 115.414,62.205 C21.1@116.486,62.205
XTAL_P: C22.1 U5.5 Y1.3 | length 6.8
  Top Layer w0.203: C22.1 110.615,61.951 111.022,61.951 ; C22.1@110.691,62.281 111.022,61.951 ; Y1.3@112.102,61.38 Y1.3 ; Y1.3@112.432,61.38 Y1.3@112.463,61.38 ; U5.5 113.058,63.966 113.138,63.886 113.138,62.354 112.164,61.38 Y1.3 ; 111.022,61.951 111.328,61.951 111.563,61.951 Y1.3
pads on no net: U5.26 U5.27 U6.7 U6.12 U6.13 U6.18 U6.46 U6.47 Y1.2 Y1.4 Y2.2 Y2.4

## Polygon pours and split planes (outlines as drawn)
GND on Top Layer "Bottom Layer-No Net" (hatched 90Degree grid 0 track 0.254, remove dead copper, pour order 1000): 100.33,93.421 100.33,60.452 129.311,60.452 129.311,93.421
GND on Bottom Layer "Bottom Layer-No Net" (hatched 90Degree grid 0 track 0.254, remove dead copper, pour order 1001): 100.33,93.421 100.33,60.452 129.286,60.452 129.286,93.421

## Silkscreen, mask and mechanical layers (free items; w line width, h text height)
Top Overlay:
  drawing of 803 lines, arcs and shapes, not listed
  text "W5500" at 111.125,86.055 h0.91
  text "STM32" at 112.751,72.288 h0.91
Bottom Overlay:
  lines w0.152: 109.728,88.697 111.023,87.401 ; 111.874,65.697 112.471,66.294
Mechanical 1:
  lines w0.203: 99.51,59.665 99.51,94.261 ; 99.517,59.663 130.106,59.663 130.106,94.234 ; 99.517,94.261 130.106,94.261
